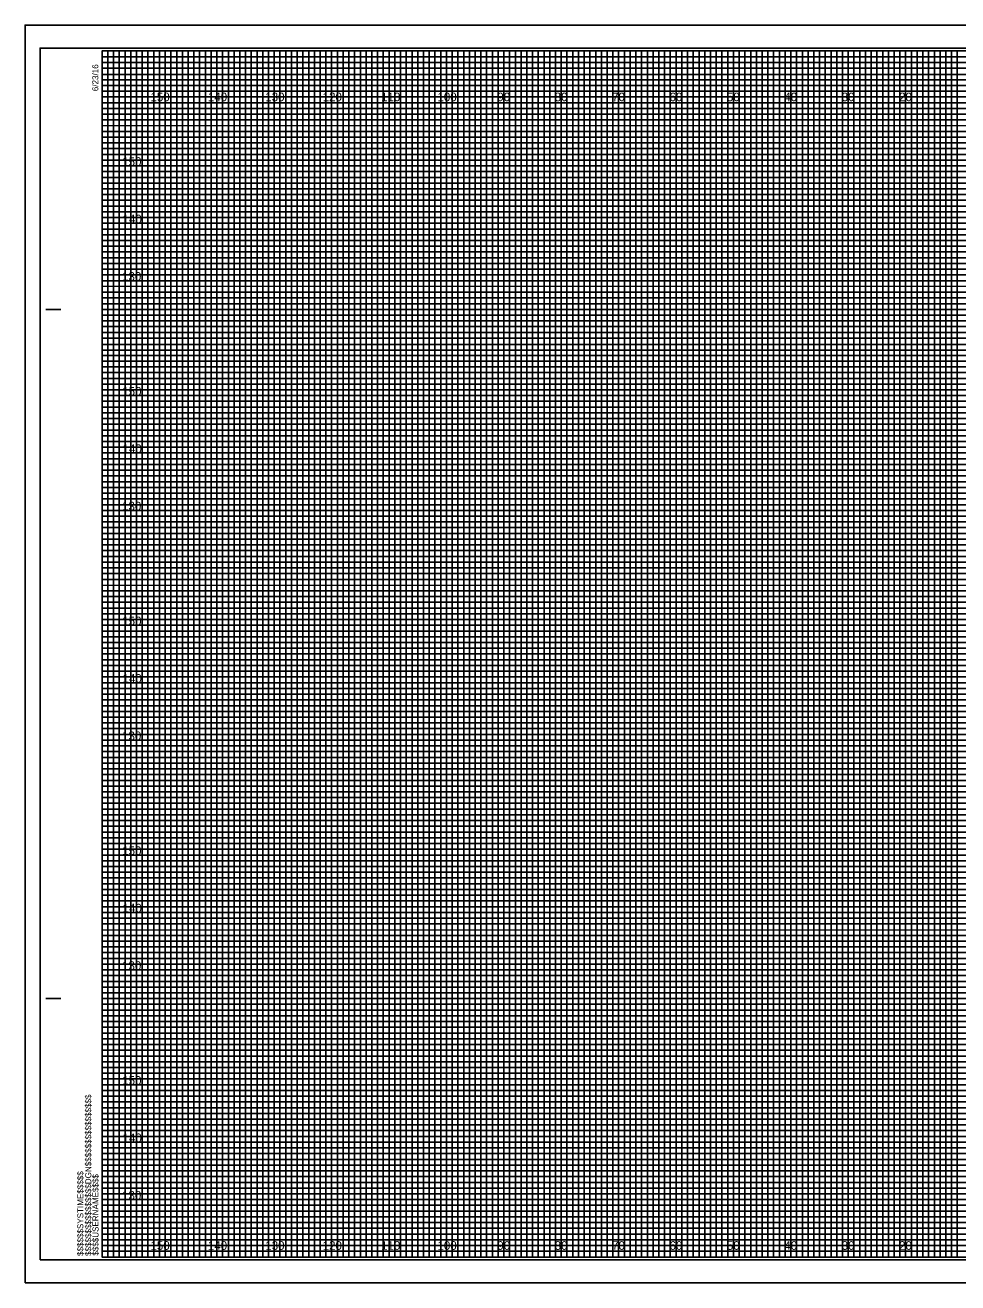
# Model space of a CAD drawing. Extents: x -13 to 323, y -5 to 2634.
# Drawn here: x -13.4 to 149.1, y 215.5 to 434.5 of the extents above; entities that cross this region are included whole.
import ezdxf

# ---------------------------------------------------------------- set-up
doc = ezdxf.new("R2010")
doc.units = 0
for name, color, linetype in [('Exist Cross Section Cell', 7, 'Continuous'), ('Exist XS Center Line Elevation Label', 7, 'Continuous'), ('Exist XS Ground Line', 7, 'Continuous'), ('Prop CMT Pvmt Surface Shoulder', 7, 'Continuous'), ('Prop CMT Pvmt Wedge Surface 3', 7, 'Continuous'), ('Prop CMT Shld Paved Course 1', 7, 'Continuous'), ('Prop CMT Shld Paved Course 2', 7, 'Continuous'), ('Prop CMT Shld Paved Course 3', 7, 'Continuous'), ('Prop CMT Slope Grass', 7, 'Continuous'), ('Prop CMT Subgrade Earthwork', 7, 'Continuous'), ('Scratch_Level_0', 7, 'Continuous')]:
    doc.layers.add(name, color=color, linetype=linetype)

msp = doc.modelspace()

# ---------------------------------------------------------------- linework, layer by layer
at = {"layer": 'Exist XS Center Line Elevation Label'}
for points in [[(0, 430), (5, 430), (5, 220), (15, 220), (15, 430), (25, 430), (25, 220), (35, 220), (35, 430), (45, 430), (45, 220), (55, 220), (55, 430), (65, 430), (65, 220), (75, 220), (75, 430), (85, 430), (85, 220), (95, 220), (95, 430), (105, 430), (105, 220), (115, 220), (115, 430), (125, 430), (125, 220), (135, 220), (135, 430), (145, 430), (145, 220), (155, 220)], [(0, 425), (275, 425)], [(0, 405), (320, 405), (320, 415), (0, 415)], [(0, 385), (320, 385), (320, 395), (0, 395)], [(0, 365), (320, 365), (320, 375), (0, 375)], [(0, 345), (320, 345), (320, 355), (0, 355)], [(0, 325), (320, 325), (320, 335), (0, 335)], [(0, 305), (320, 305), (320, 315), (0, 315)], [(0, 285), (320, 285), (320, 295), (0, 295)], [(0, 265), (320, 265), (320, 275), (0, 275)], [(0, 245), (320, 245), (320, 255), (0, 255)], [(0, 225), (320, 225), (320, 235), (0, 235)]]:
    msp.add_lwpolyline(points, dxfattribs=at)
at = {"layer": 'Exist XS Ground Line'}
for p, q in [((10, 430), (0, 430)), ((10, 220), (10, 430)), ((30, 430), (20, 430)), ((20, 430), (20, 220)), ((30, 220), (30, 430)), ((50, 430), (40, 430)), ((40, 430), (40, 220)), ((50, 220), (50, 430)), ((70, 430), (60, 430)), ((60, 430), (60, 220)), ((70, 220), (70, 430)), ((90, 430), (80, 430)), ((80, 430), (80, 220)), ((90, 220), (90, 430)), ((110, 430), (100, 430)), ((100, 430), (100, 220)), ((110, 220), (110, 430)), ((130, 430), (120, 430)), ((120, 430), (120, 220)), ((130, 220), (130, 430)), ((150, 430), (140, 430)), ((140, 430), (140, 220)), ((20, 220), (10, 220)), ((40, 220), (30, 220)), ((60, 220), (50, 220)), ((80, 220), (70, 220)), ((100, 220), (90, 220)), ((120, 220), (110, 220)), ((140, 220), (130, 220))]:
    msp.add_line(p, q, dxfattribs=at)
for points in [[(0, 420), (320, 420), (320, 410), (0, 410)], [(0, 400), (320, 400), (320, 390), (0, 390)], [(0, 380), (320, 380), (320, 370), (0, 370)], [(0, 360), (320, 360), (320, 350), (0, 350)], [(0, 340), (320, 340), (320, 330), (0, 330)], [(0, 320), (320, 320), (320, 310), (0, 310)], [(0, 300), (320, 300), (320, 290), (0, 290)], [(0, 280), (320, 280), (320, 270), (0, 270)], [(0, 260), (320, 260), (320, 250), (0, 250)], [(0, 240), (320, 240), (320, 230), (0, 230)]]:
    msp.add_lwpolyline(points, dxfattribs=at)
at = {"layer": 'Prop CMT Pvmt Surface Shoulder'}
for points in [[(0, 220), (1, 220), (1, 430), (2, 430), (2, 220)], [(2, 220), (3, 220), (3, 430), (4, 430), (4, 220)], [(5, 220), (6, 220), (6, 430), (7, 430), (7, 220)], [(7, 220), (8, 220), (8, 430), (9, 430), (9, 220)], [(10, 220), (11, 220), (11, 430), (12, 430), (12, 220)], [(12, 220), (13, 220), (13, 430), (14, 430), (14, 220)], [(15, 220), (16, 220), (16, 430), (17, 430), (17, 220)], [(17, 220), (18, 220), (18, 430), (19, 430), (19, 220)], [(20, 220), (21, 220), (21, 430), (22, 430), (22, 220)], [(22, 220), (23, 220), (23, 430), (24, 430), (24, 220)], [(25, 220), (26, 220), (26, 430), (27, 430), (27, 220)], [(27, 220), (28, 220), (28, 430), (29, 430), (29, 220)], [(30, 220), (31, 220), (31, 430), (32, 430), (32, 220)], [(32, 220), (33, 220), (33, 430), (34, 430), (34, 220)], [(35, 220), (36, 220), (36, 430), (37, 430), (37, 220)], [(37, 220), (38, 220), (38, 430), (39, 430), (39, 220)], [(40, 220), (41, 220), (41, 430), (42, 430), (42, 220)], [(42, 220), (43, 220), (43, 430), (44, 430), (44, 220)], [(45, 220), (46, 220), (46, 430), (47, 430), (47, 220)], [(47, 220), (48, 220), (48, 430), (49, 430), (49, 220)], [(50, 220), (51, 220), (51, 430), (52, 430), (52, 220)], [(52, 220), (53, 220), (53, 430), (54, 430), (54, 220)], [(55, 220), (56, 220), (56, 430), (57, 430), (57, 220)], [(57, 220), (58, 220), (58, 430), (59, 430), (59, 220)], [(60, 220), (61, 220), (61, 430), (62, 430), (62, 220)], [(62, 220), (63, 220), (63, 430), (64, 430), (64, 220)], [(65, 220), (66, 220), (66, 430), (67, 430), (67, 220)], [(67, 220), (68, 220), (68, 430), (69, 430), (69, 220)], [(70, 220), (71, 220), (71, 430), (72, 430), (72, 220)], [(72, 220), (73, 220), (73, 430), (74, 430), (74, 220)], [(75, 220), (76, 220), (76, 430), (77, 430), (77, 220)], [(77, 220), (78, 220), (78, 430), (79, 430), (79, 220)], [(80, 220), (81, 220), (81, 430), (82, 430), (82, 220)], [(82, 220), (83, 220), (83, 430), (84, 430), (84, 220)], [(85, 220), (86, 220), (86, 430), (87, 430), (87, 220)], [(87, 220), (88, 220), (88, 430), (89, 430), (89, 220)], [(90, 220), (91, 220), (91, 430), (92, 430), (92, 220)], [(92, 220), (93, 220), (93, 430), (94, 430), (94, 220)], [(95, 220), (96, 220), (96, 430), (97, 430), (97, 220)], [(97, 220), (98, 220), (98, 430), (99, 430), (99, 220)], [(100, 220), (101, 220), (101, 430), (102, 430), (102, 220)], [(102, 220), (103, 220), (103, 430), (104, 430), (104, 220)], [(105, 220), (106, 220), (106, 430), (107, 430), (107, 220)], [(107, 220), (108, 220), (108, 430), (109, 430), (109, 220)], [(110, 220), (111, 220), (111, 430), (112, 430), (112, 220)], [(112, 220), (113, 220), (113, 430), (114, 430), (114, 220)], [(115, 220), (116, 220), (116, 430), (117, 430), (117, 220)], [(117, 220), (118, 220), (118, 430), (119, 430), (119, 220)], [(120, 220), (121, 220), (121, 430), (122, 430), (122, 220)], [(122, 220), (123, 220), (123, 430), (124, 430), (124, 220)], [(125, 220), (126, 220), (126, 430), (127, 430), (127, 220)], [(127, 220), (128, 220), (128, 430), (129, 430), (129, 220)], [(130, 220), (131, 220), (131, 430), (132, 430), (132, 220)], [(132, 220), (133, 220), (133, 430), (134, 430), (134, 220)], [(135, 220), (136, 220), (136, 430), (137, 430), (137, 220)], [(137, 220), (138, 220), (138, 430), (139, 430), (139, 220)], [(140, 220), (141, 220), (141, 430), (142, 430), (142, 220)], [(142, 220), (143, 220), (143, 430), (144, 430), (144, 220)], [(145, 220), (146, 220), (146, 430), (147, 430), (147, 220)], [(147, 220), (148, 220), (148, 430), (149, 430), (149, 220)]]:
    msp.add_lwpolyline(points, dxfattribs=at)
at = {"layer": 'Prop CMT Pvmt Wedge Surface 3'}
for p, q in [((-9.8, 385), (-7.3, 385)), ((-9.7, 385), (-7.2, 385)), ((-9.8, 265), (-7.3, 265)), ((-9.7, 265), (-7.2, 265)), ((0, 220), (0, 220)), ((0, 220), (0, 220)), ((0, 220), (0, 220)), ((0, 220), (0, 220)), ((0, 220), (0, 220)), ((0, 220), (0, 220)), ((0, 220), (0, 220))]:
    msp.add_line(p, q, dxfattribs=at)
msp.add_lwpolyline([(320, 430), (0, 430), (0, 220), (320, 220)], close=True, dxfattribs=at)
at = {"layer": 'Prop CMT Shld Paved Course 1'}
for p, q in [((10, 220), (10, 430)), ((20, 220), (20, 430)), ((30, 220), (30, 430)), ((40, 220), (40, 430)), ((50, 220), (50, 430)), ((60, 220), (60, 430)), ((70, 220), (70, 430)), ((80, 220), (80, 430)), ((90, 220), (90, 430)), ((100, 220), (100, 430)), ((110, 220), (110, 430)), ((120, 220), (120, 430)), ((130, 220), (130, 430)), ((140, 220), (140, 430)), ((0, 420), (320, 420)), ((0, 410), (320, 410)), ((0, 400), (320, 400)), ((0, 390), (320, 390)), ((0, 380), (320, 380)), ((0, 370), (320, 370)), ((0, 360), (320, 360)), ((0, 350), (320, 350)), ((0, 340), (320, 340)), ((0, 330), (320, 330)), ((0, 320), (320, 320)), ((0, 310), (320, 310)), ((0, 300), (320, 300)), ((0, 290), (320, 290)), ((0, 280), (320, 280)), ((0, 270), (320, 270)), ((0, 260), (320, 260)), ((0, 250), (320, 250)), ((0, 240), (320, 240)), ((0, 230), (320, 230))]:
    msp.add_line(p, q, dxfattribs=at)
at = {"layer": 'Prop CMT Shld Paved Course 2'}
for p, q in [((323.3, 434.5), (-13.4, 434.5)), ((-13.4, 434.5), (-13.4, 215.5)), ((-13.4, 215.5), (323.3, 215.5))]:
    msp.add_line(p, q, dxfattribs=at)
at = {"layer": 'Prop CMT Slope Grass'}
msp.add_lwpolyline([(-10.8, 219.5), (322.4, 219.5), (322.4, 430.5), (-10.8, 430.5)], close=True, dxfattribs=at)
at = {"layer": 'Prop CMT Subgrade Earthwork'}
msp.add_lwpolyline([(-13.4, 215.5), (323.3, 215.5), (323.3, 434.5), (-13.4, 434.5)], close=True, dxfattribs=at)
at = {"layer": 'Scratch_Level_0'}
for p, q in [((0, 429), (260, 429)), ((260, 427.98), (0, 427.98)), ((0, 427.98), (0, 427)), ((0, 427), (260, 427)), ((260, 425.89), (0, 425.89)), ((0, 425.89), (0, 424)), ((0, 424), (320, 424))]:
    msp.add_line(p, q, dxfattribs=at)
for points in [[(0, 423), (270, 423), (320, 423), (320, 422), (0, 422)], [(0, 421), (320, 421), (320, 419), (0, 419)], [(0, 418), (320, 418), (320, 417), (0, 416.98)], [(0, 416), (320, 416), (320, 414), (0, 414)], [(0, 413), (320, 413), (320, 412), (0, 412)], [(0, 411), (320, 411), (320, 409), (0, 409)], [(0, 408), (320, 408), (320, 407), (0, 407)], [(0, 406), (320, 406), (320, 404), (0, 404)], [(0, 403), (320, 403), (320, 402), (0, 402)], [(0, 401), (320, 401), (320, 399), (0, 399)], [(0, 398), (320, 398), (320, 397), (0, 397)], [(0, 396), (320, 396), (320, 393.95), (320, 393), (320, 392), (0, 392)], [(0, 394), (320, 394), (320, 393), (0, 393)], [(0, 391), (320, 391), (320, 389), (0, 389.03)], [(0, 389.03), (320, 389), (320, 388), (0, 388)], [(0, 387), (320, 387), (320, 386), (0, 386)], [(0, 384), (320, 384), (320, 383), (0, 383)], [(0, 382), (320, 382), (320, 381), (0, 381)], [(-0.07, 378.89), (320, 378.89), (320, 377.88), (-0.07, 377.88)], [(0, 377), (320, 377), (320, 376), (0, 376)], [(0, 374), (320, 374), (320, 373), (0, 373)], [(0, 372), (320, 372), (320, 371), (0, 371)], [(0, 369), (320, 369), (320, 368), (0, 368)], [(0, 367), (320, 367), (320, 366), (0, 366)], [(0, 364), (320, 364), (320, 363), (0, 363)], [(0, 362), (320, 362), (320, 361), (0, 361)], [(0, 359), (320, 359), (319.99, 357.98), (0, 358)], [(0, 357), (320, 357), (320, 356), (0, 356)], [(0, 354), (320, 354), (320, 353), (0, 353)], [(0, 352), (320, 352), (320, 351), (0, 351)], [(0, 349), (320, 349), (320, 348), (0, 348)], [(0, 347), (320, 347), (320, 346), (0, 346)], [(0, 344), (320, 344), (320, 343), (0, 343)], [(0, 342), (320, 342), (320, 341), (0, 341)], [(0, 339), (320, 339), (320, 338), (0, 338)], [(0, 336.99), (320.07, 336.91), (320, 336), (0, 336)], [(0, 334), (320, 334), (320, 333), (0, 333)], [(0, 332), (320, 332), (320, 331), (0, 331)], [(0, 329), (320, 329), (320, 328), (0, 328)], [(0, 327), (320, 327), (320, 326), (0, 326)], [(0, 324), (320, 324), (320, 323), (0, 323)], [(0, 322), (320, 322), (320, 321), (0, 321)], [(0, 319), (320, 319), (320, 318), (0, 318)], [(0, 317), (320, 317), (320, 316), (0, 316)], [(0, 314), (320, 314), (320, 313), (0, 313)], [(0, 312), (320, 312), (320, 311), (0, 311)], [(0, 309), (320, 309), (320, 308), (0, 308)], [(0, 307), (320, 307), (320, 306), (0, 306)], [(0, 304), (320, 304), (320, 303), (0, 303)], [(0, 302), (320, 302), (320, 301), (0, 301)], [(0, 299), (320, 299), (319.99, 297.98), (0, 298)], [(0, 297), (320, 297), (320, 296), (0, 296)], [(0, 294), (320, 294), (320, 293), (0, 293)], [(0, 292), (320, 292), (320, 291), (0, 291)], [(0, 289), (320, 289), (320, 288), (0, 288)], [(0, 287), (320, 287), (320, 286), (0, 286)], [(0, 284), (320, 284), (320, 283), (0, 283)], [(0, 282), (320, 282), (320, 281), (0, 281)], [(0, 279), (320, 279), (320, 278), (0, 278)], [(0, 276.99), (320.07, 276.91), (320, 276), (0, 276)], [(0, 274), (320, 274), (320, 273), (0, 273)], [(0, 272), (320, 272), (320, 271), (0, 271)], [(0, 269), (320, 269), (320, 268), (0, 268)], [(0, 267), (320, 267), (320, 266), (0, 266)], [(0, 264), (320, 264), (320, 263), (0, 263)], [(0, 262), (320, 262), (320, 261), (0, 261)], [(0, 259), (320, 259), (320, 258), (0, 258)], [(0, 257), (320, 257), (320, 256), (0, 256)], [(0, 254), (320, 254), (320, 253), (0, 253)], [(0, 252), (320, 252), (320, 251), (0, 251)], [(0, 249), (320, 249), (320, 248), (0, 248)], [(0, 247), (320, 247), (320, 246), (0, 246)], [(0, 244), (320, 244), (320, 243), (0, 243)], [(0, 242), (320, 242), (320, 241), (0, 241)], [(0, 239), (320, 239), (320, 238), (0, 238)], [(0, 237), (320, 237), (320, 236), (0, 236)], [(0, 234), (320, 234), (320, 233), (0, 233)], [(0, 232), (320, 232), (320, 231), (0, 231)], [(0, 229), (320, 229), (320, 228), (0, 228)], [(0, 227), (320, 227), (320, 226), (0, 226)], [(0, 224), (320, 224), (320, 223), (0, 223)], [(0, 222), (320, 222), (320, 221), (0, 221)]]:
    msp.add_lwpolyline(points, dxfattribs=at)

# ---------------------------------------------------------------- texts
at = {"layer": 'Exist Cross Section Cell'}
for s, p in [('150', (8.44, 421.25)), ('140', (18.44, 421.25)), ('130', (28.44, 421.25)), ('120', (38.44, 421.25)), ('110', (48.62, 421.25)), ('100', (58.44, 421.25)), ('90', (68.86, 421.25)), ('80', (78.86, 421.25)), ('70', (88.86, 421.25)), ('60', (98.86, 421.25)), ('50', (108.86, 421.25)), ('40', (118.86, 421.25)), ('30', (128.86, 421.25)), ('20', (138.86, 421.25)), ('150', (8.44, 221.25)), ('140', (18.44, 221.25)), ('130', (28.44, 221.25)), ('120', (38.44, 221.25)), ('110', (48.62, 221.25)), ('100', (58.44, 221.25)), ('90', (68.86, 221.25)), ('80', (78.86, 221.25)), ('70', (88.86, 221.25)), ('60', (98.86, 221.25)), ('50', (108.86, 221.25)), ('40', (118.86, 221.25)), ('30', (128.86, 221.25)), ('20', (138.86, 221.25))]:
    msp.add_text(s, height=1.5, dxfattribs=at).set_placement(p)
at = {"layer": 'Prop CMT Pvmt Wedge Surface 3'}
for s, p in [('6/23/16', (-0.65, 423)), ('$$$$$$$$$$$$$$$$DGN$$$$$$$$$$$$$$$$', (-1.88, 220.18)), ('$$$$$$SYSTIME$$$$$', (-3.26, 220.18)), ('$$$$USERNAME$$$$', (-0.62, 220.23))]:
    msp.add_text(s, height=1.05, rotation=90, dxfattribs=at).set_placement(p)
at = {"layer": 'Prop CMT Shld Paved Course 3'}
for s, p in [('150', (3.52, 410)), ('140', (3.57, 400)), ('130', (3.49, 390)), ('150', (3.52, 370)), ('140', (3.57, 360)), ('130', (3.49, 350)), ('150', (3.52, 330)), ('140', (3.57, 320)), ('130', (3.49, 310)), ('150', (3.52, 290)), ('140', (3.57, 280)), ('130', (3.49, 270)), ('150', (3.52, 250)), ('140', (3.57, 240)), ('130', (3.49, 230))]:
    msp.add_text(s, height=1.5, dxfattribs=at).set_placement(p)

doc.saveas('drawing.dxf')
